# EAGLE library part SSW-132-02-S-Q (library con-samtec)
THROUGH-HOLE .025" SQ POST SOCKET Source: Samtec SSW.pdf
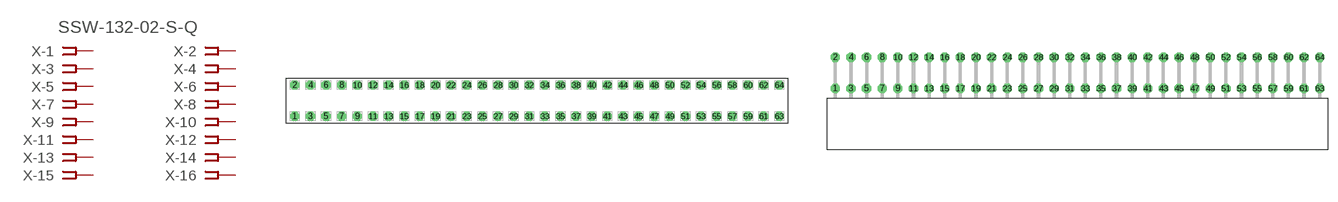
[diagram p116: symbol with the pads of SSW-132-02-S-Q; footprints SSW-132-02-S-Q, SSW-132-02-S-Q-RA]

Designator prefix X; gates -1=FPINV -2=FPIN -3=FPIN -4=FPIN -5=FPIN -6=FPIN -7=FPIN -8=FPIN -9=FPIN -10=FPIN -11=FPIN -12=FPIN -13=FPIN -14=FPIN -15=FPIN -16=FPIN -17=FPIN -18=FPIN -19=FPIN -20=FPIN -21=FPIN -22=FPIN -23=FPIN -24=FPIN -25=FPIN -26=FPIN -27=FPIN -28=FPIN -29=FPIN -30=FPIN -31=FPIN -32=FPIN -33=FPIN -34=FPIN -35=FPIN -36=FPIN -37=FPIN -38=FPIN -39=FPIN -40=FPIN -41=FPIN -42=FPIN -43=FPIN -44=FPIN -45=FPIN -46=FPIN -47=FPIN -48=FPIN -49=FPIN -50=FPIN -51=FPIN -52=FPIN -53=FPIN -54=FPIN -55=FPIN -56=FPIN -57=FPIN -58=FPIN -59=FPIN -60=FPIN -61=FPIN -62=FPIN -63=FPIN -64=FPIN

## SSW-132-02-S-Q (MPN: SSW-132-02-S-Q; OC_FARNELL: unknown; OC_NEWARK: 83P0340)  [SSW-132-02-S-Q]
1  -1:1  pas
2  -2:1  pas
3  -3:1  pas
4  -4:1  pas
5  -5:1  pas
6  -6:1  pas
7  -7:1  pas
8  -8:1  pas
9  -9:1  pas
10  -10:1  pas
11  -11:1  pas
12  -12:1  pas
13  -13:1  pas
14  -14:1  pas
15  -15:1  pas
16  -16:1  pas
17  -17:1  pas
18  -18:1  pas
19  -19:1  pas
20  -20:1  pas
21  -21:1  pas
22  -22:1  pas
23  -23:1  pas
24  -24:1  pas
25  -25:1  pas
26  -26:1  pas
27  -27:1  pas
28  -28:1  pas
29  -29:1  pas
30  -30:1  pas
31  -31:1  pas
32  -32:1  pas
33  -33:1  pas
34  -34:1  pas
35  -35:1  pas
36  -36:1  pas
37  -37:1  pas
38  -38:1  pas
39  -39:1  pas
40  -40:1  pas
41  -41:1  pas
42  -42:1  pas
43  -43:1  pas
44  -44:1  pas
45  -45:1  pas
46  -46:1  pas
47  -47:1  pas
48  -48:1  pas
49  -49:1  pas
50  -50:1  pas
51  -51:1  pas
52  -52:1  pas
53  -53:1  pas
54  -54:1  pas
55  -55:1  pas
56  -56:1  pas
57  -57:1  pas
58  -58:1  pas
59  -59:1  pas
60  -60:1  pas
61  -61:1  pas
62  -62:1  pas
63  -63:1  pas
64  -64:1  pas

## SSW-132-02-S-QRA (MPN: SSW-132-02-S-Q-RA; OC_FARNELL: unknown; OC_NEWARK: 83P0341)  [SSW-132-02-S-Q-RA]
Pads as for SSW-132-02-S-Q

## Footprint SSW-132-02-S-Q (pad centres in mm)
THROUGH-HOLE .025" SQ POST SOCKET Source: Samtec SSW.pdf
drill 1 pad 1.5 octagon: 1 -39.37,-2.54; 2 -39.37,2.54; 3 -36.83,-2.54; 4 -36.83,2.54; 5 -34.29,-2.54; 6 -34.29,2.54; 7 -31.75,-2.54; 8 -31.75,2.54; 9 -29.21,-2.54; 10 -29.21,2.54; 11 -26.67,-2.54; 12 -26.67,2.54; 13 -24.13,-2.54; 14 -24.13,2.54; 15 -21.59,-2.54; 16 -21.59,2.54; 17 -19.05,-2.54; 18 -19.05,2.54; 19 -16.51,-2.54; 20 -16.51,2.54; 21 -13.97,-2.54; 22 -13.97,2.54; 23 -11.43,-2.54; 24 -11.43,2.54; 25 -8.89,-2.54; 26 -8.89,2.54; 27 -6.35,-2.54; 28 -6.35,2.54; 29 -3.81,-2.54; 30 -3.81,2.54; 31 -1.27,-2.54; 32 -1.27,2.54; 33 1.27,-2.54; 34 1.27,2.54; 35 3.81,-2.54; 36 3.81,2.54; 37 6.35,-2.54; 38 6.35,2.54; 39 8.89,-2.54; 40 8.89,2.54; 41 11.43,-2.54; 42 11.43,2.54; 43 13.97,-2.54; 44 13.97,2.54; 45 16.51,-2.54; 46 16.51,2.54; 47 19.05,-2.54; 48 19.05,2.54; 49 21.59,-2.54; 50 21.59,2.54; 51 24.13,-2.54; 52 24.13,2.54; 53 26.67,-2.54; 54 26.67,2.54; 55 29.21,-2.54; 56 29.21,2.54; 57 31.75,-2.54; 58 31.75,2.54; 59 34.29,-2.54; 60 34.29,2.54; 61 36.83,-2.54; 62 36.83,2.54; 63 39.37,-2.54; 64 39.37,2.54

## Footprint SSW-132-02-S-Q-RA (pad centres in mm)
THROUGH-HOLE .025" SQ POST SOCKET Source: Samtec SSW.pdf
drill 1 pad 1.5 octagon: 1 -39.37,1.524; 2 -39.37,6.604; 3 -36.83,1.524; 4 -36.83,6.604; 5 -34.29,1.524; 6 -34.29,6.604; 7 -31.75,1.524; 8 -31.75,6.604; 9 -29.21,1.524; 10 -29.21,6.604; 11 -26.67,1.524; 12 -26.67,6.604; 13 -24.13,1.524; 14 -24.13,6.604; 15 -21.59,1.524; 16 -21.59,6.604; 17 -19.05,1.524; 18 -19.05,6.604; 19 -16.51,1.524; 20 -16.51,6.604; 21 -13.97,1.524; 22 -13.97,6.604; 23 -11.43,1.524; 24 -11.43,6.604; 25 -8.89,1.524; 26 -8.89,6.604; 27 -6.35,1.524; 28 -6.35,6.604; 29 -3.81,1.524; 30 -3.81,6.604; 31 -1.27,1.524; 32 -1.27,6.604; 33 1.27,1.524; 34 1.27,6.604; 35 3.81,1.524; 36 3.81,6.604; 37 6.35,1.524; 38 6.35,6.604; 39 8.89,1.524; 40 8.89,6.604; 41 11.43,1.524; 42 11.43,6.604; 43 13.97,1.524; 44 13.97,6.604; 45 16.51,1.524; 46 16.51,6.604; 47 19.05,1.524; 48 19.05,6.604; 49 21.59,1.524; 50 21.59,6.604; 51 24.13,1.524; 52 24.13,6.604; 53 26.67,1.524; 54 26.67,6.604; 55 29.21,1.524; 56 29.21,6.604; 57 31.75,1.524; 58 31.75,6.604; 59 34.29,1.524; 60 34.29,6.604; 61 36.83,1.524; 62 36.83,6.604; 63 39.37,1.524; 64 39.37,6.604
